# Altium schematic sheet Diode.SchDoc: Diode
size A; DocumentNumber: 1; SheetNumber: 1; SheetTotal: 1
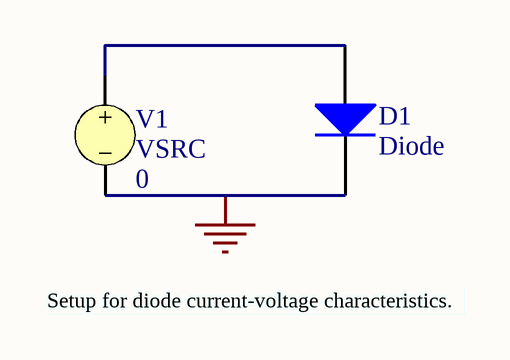
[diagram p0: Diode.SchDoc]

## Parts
D1  Diode  [DSO-C2/X3.3]
V1  VSRC  value 0

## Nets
GND: D1.2(K) V1.2
NetD1_1: D1.1(A) V1.1

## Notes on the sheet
- Setup for diode current-voltage characteristics.

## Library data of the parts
D1 = Diode: Default Diode
V1 = VSRC: Voltage Source; Manufacturer: Generic Components; Class: Simulation; Note: PCB Footprint - Not required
